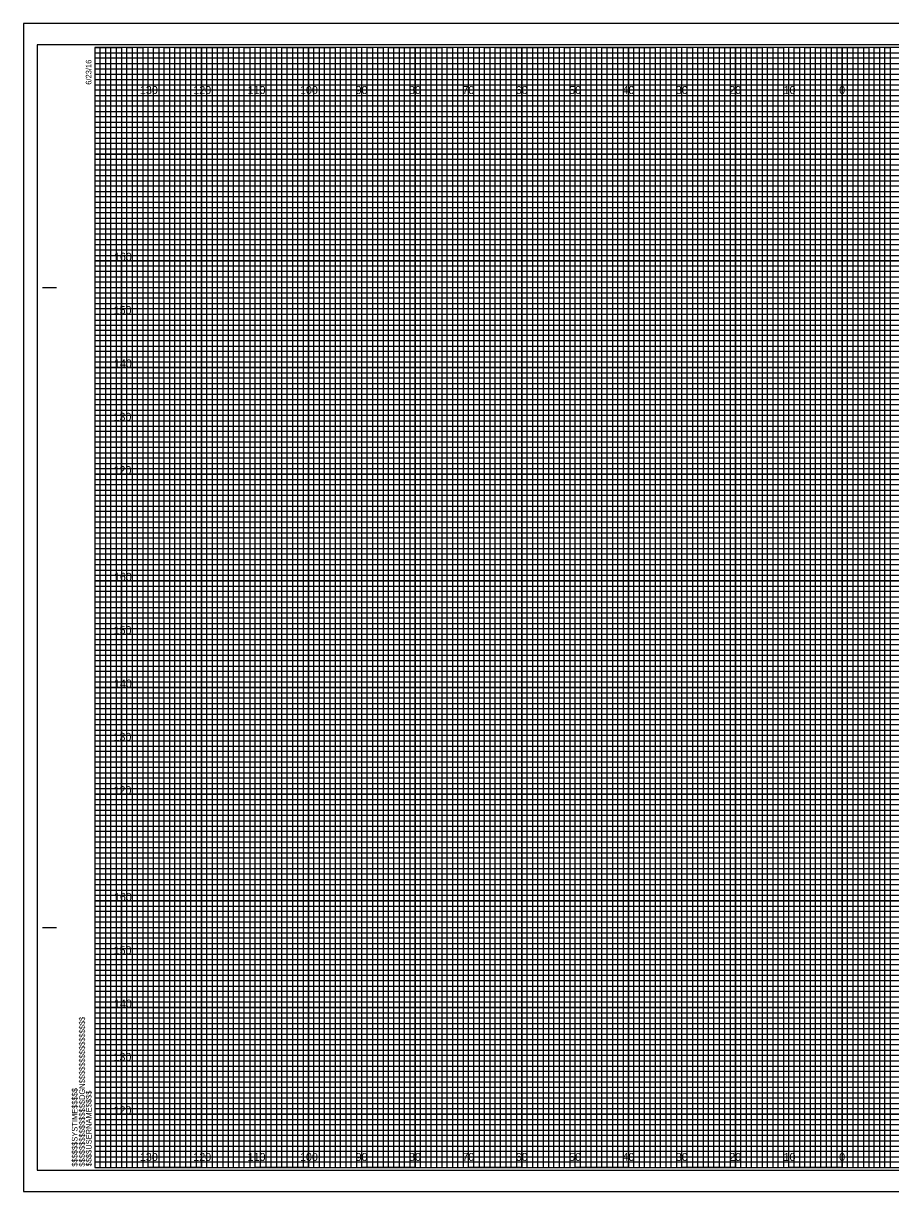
# Model space of a CAD drawing. Extents: x -13 to 323, y -5 to 3294.
# Drawn here: x -13.4 to 149.1, y 1315.5 to 1534.5 of the extents above; entities that cross this region are included whole.
import ezdxf

# ---------------------------------------------------------------- set-up
doc = ezdxf.new("R2010")
doc.units = 0
for name, color, linetype in [('Prop XS Elevation Labels', 7, 'Continuous'), ('Prop XS Offset Labels', 7, 'Continuous'), ('Scratch_Level_0', 7, 'Continuous'), ('Sheet Cross Section CELL', 7, 'Continuous'), ('Sheet Cross Section Grid Major CELL', 7, 'Continuous'), ('Sheet Cross Section Grid Middle CELL', 7, 'Continuous'), ('Sheet Cross Section Grid Minor 1 CELL', 7, 'Continuous'), ('Sheet Cross Section Grid Minor 2 CELL', 7, 'Continuous'), ('Sheet Cutting Line CELL', 7, 'Continuous'), ('Sheet DOT Grid CELL', 7, 'Continuous'), ('Sheet Plot Border Inside CELL', 7, 'Continuous'), ('Sheet Plot Border Outside CELL', 7, 'Continuous')]:
    doc.layers.add(name, color=color, linetype=linetype)

msp = doc.modelspace()

# ---------------------------------------------------------------- linework, layer by layer
at = {"layer": 'Scratch_Level_0'}
for points in [[(5, 1490), (310, 1490), (310, 1450), (5, 1450)], [(5, 1430), (315, 1430), (315, 1390), (5, 1390)], [(5, 1370), (315, 1370), (315, 1330), (5, 1330)]]:
    msp.add_lwpolyline(points, close=True, dxfattribs=at)
at = {"layer": 'Sheet Cross Section CELL'}
for p, q in [((-9.8, 1485), (-7.3, 1485)), ((-9.7, 1485), (-7.2, 1485)), ((-9.8, 1365), (-7.3, 1365)), ((-9.7, 1365), (-7.2, 1365)), ((0, 1320), (0, 1320)), ((0, 1320), (0, 1320)), ((0, 1320), (0, 1320)), ((0, 1320), (0, 1320)), ((0, 1320), (0, 1320)), ((0, 1320), (0, 1320)), ((0, 1320), (0, 1320))]:
    msp.add_line(p, q, dxfattribs=at)
msp.add_lwpolyline([(320, 1530), (0, 1530), (0, 1320), (320, 1320)], close=True, dxfattribs=at)
at = {"layer": 'Sheet Cross Section Grid Major CELL'}
for p, q in [((10, 1530), (0, 1530)), ((10, 1320), (10, 1530)), ((30, 1530), (20, 1530)), ((20, 1530), (20, 1320)), ((30, 1320), (30, 1530)), ((50, 1530), (40, 1530)), ((40, 1530), (40, 1320)), ((50, 1320), (50, 1530)), ((70, 1530), (60, 1530)), ((60, 1530), (60, 1320)), ((70, 1320), (70, 1530)), ((90, 1530), (80, 1530)), ((80, 1530), (80, 1320)), ((90, 1320), (90, 1530)), ((110, 1530), (100, 1530)), ((100, 1530), (100, 1320)), ((110, 1320), (110, 1530)), ((130, 1530), (120, 1530)), ((120, 1530), (120, 1320)), ((130, 1320), (130, 1530)), ((150, 1530), (140, 1530)), ((140, 1530), (140, 1320)), ((20, 1320), (10, 1320)), ((40, 1320), (30, 1320)), ((60, 1320), (50, 1320)), ((80, 1320), (70, 1320)), ((100, 1320), (90, 1320)), ((120, 1320), (110, 1320)), ((140, 1320), (130, 1320))]:
    msp.add_line(p, q, dxfattribs=at)
for points in [[(0, 1520), (320, 1520), (320, 1510), (0, 1510)], [(0, 1500), (320, 1500), (320, 1490), (0, 1490)], [(0, 1480), (320, 1480), (320, 1470), (0, 1470)], [(0, 1460), (320, 1460), (320, 1450), (0, 1450)], [(0, 1440), (320, 1440), (320, 1430), (0, 1430)], [(0, 1420), (320, 1420), (320, 1410), (0, 1410)], [(0, 1400), (320, 1400), (320, 1390), (0, 1390)], [(0, 1380), (320, 1380), (320, 1370), (0, 1370)], [(0, 1360), (320, 1360), (320, 1350), (0, 1350)], [(0, 1340), (320, 1340), (320, 1330), (0, 1330)]]:
    msp.add_lwpolyline(points, dxfattribs=at)
at = {"layer": 'Sheet Cross Section Grid Middle CELL'}
for points in [[(0, 1530), (5, 1530), (5, 1320), (15, 1320), (15, 1530), (25, 1530), (25, 1320), (35, 1320), (35, 1530), (45, 1530), (45, 1320), (55, 1320), (55, 1530), (65, 1530), (65, 1320), (75, 1320), (75, 1530), (85, 1530), (85, 1320), (95, 1320), (95, 1530), (105, 1530), (105, 1320), (115, 1320), (115, 1530), (125, 1530), (125, 1320), (135, 1320), (135, 1530), (145, 1530), (145, 1320), (155, 1320)], [(0, 1525), (275, 1525)], [(0, 1505), (320, 1505), (320, 1515), (0, 1515)], [(0, 1485), (320, 1485), (320, 1495), (0, 1495)], [(0, 1465), (320, 1465), (320, 1475), (0, 1475)], [(0, 1445), (320, 1445), (320, 1455), (0, 1455)], [(0, 1425), (320, 1425), (320, 1435), (0, 1435)], [(0, 1405), (320, 1405), (320, 1415), (0, 1415)], [(0, 1385), (320, 1385), (320, 1395), (0, 1395)], [(0, 1365), (320, 1365), (320, 1375), (0, 1375)], [(0, 1345), (320, 1345), (320, 1355), (0, 1355)], [(0, 1325), (320, 1325), (320, 1335), (0, 1335)]]:
    msp.add_lwpolyline(points, dxfattribs=at)
at = {"layer": 'Sheet Cross Section Grid Minor 1 CELL'}
for p, q in [((0, 1529), (260, 1529)), ((260, 1527.98), (0, 1527.98)), ((0, 1527.98), (0, 1527)), ((0, 1527), (260, 1527)), ((260, 1525.89), (0, 1525.89)), ((0, 1525.89), (0, 1524)), ((0, 1524), (320, 1524))]:
    msp.add_line(p, q, dxfattribs=at)
for points in [[(0, 1523), (270, 1523), (320, 1523), (320, 1522), (0, 1522)], [(0, 1521), (320, 1521), (320, 1519), (0, 1519)], [(0, 1518), (320, 1518), (320, 1517), (0, 1516.98)], [(0, 1516), (320, 1516), (320, 1514), (0, 1514)], [(0, 1513), (320, 1513), (320, 1512), (0, 1512)], [(0, 1511), (320, 1511), (320, 1509), (0, 1509)], [(0, 1508), (320, 1508), (320, 1507), (0, 1507)], [(0, 1506), (320, 1506), (320, 1504), (0, 1504)], [(0, 1503), (320, 1503), (320, 1502), (0, 1502)], [(0, 1501), (320, 1501), (320, 1499), (0, 1499)], [(0, 1498), (320, 1498), (320, 1497), (0, 1497)], [(0, 1496), (320, 1496), (320, 1493.95), (320, 1493), (320, 1492), (0, 1492)], [(0, 1494), (320, 1494), (320, 1493), (0, 1493)], [(0, 1491), (320, 1491), (320, 1489), (0, 1489.03)], [(0, 1489.03), (320, 1489), (320, 1488), (0, 1488)], [(0, 1487), (320, 1487), (320, 1486), (0, 1486)], [(0, 1484), (320, 1484), (320, 1483), (0, 1483)], [(0, 1482), (320, 1482), (320, 1481), (0, 1481)], [(-0.07, 1478.89), (320, 1478.89), (320, 1477.88), (-0.07, 1477.88)], [(0, 1477), (320, 1477), (320, 1476), (0, 1476)], [(0, 1474), (320, 1474), (320, 1473), (0, 1473)], [(0, 1472), (320, 1472), (320, 1471), (0, 1471)], [(0, 1469), (320, 1469), (320, 1468), (0, 1468)], [(0, 1467), (320, 1467), (320, 1466), (0, 1466)], [(0, 1464), (320, 1464), (320, 1463), (0, 1463)], [(0, 1462), (320, 1462), (320, 1461), (0, 1461)], [(0, 1459), (320, 1459), (319.99, 1457.98), (0, 1458)], [(0, 1457), (320, 1457), (320, 1456), (0, 1456)], [(0, 1454), (320, 1454), (320, 1453), (0, 1453)], [(0, 1452), (320, 1452), (320, 1451), (0, 1451)], [(0, 1449), (320, 1449), (320, 1448), (0, 1448)], [(0, 1447), (320, 1447), (320, 1446), (0, 1446)], [(0, 1444), (320, 1444), (320, 1443), (0, 1443)], [(0, 1442), (320, 1442), (320, 1441), (0, 1441)], [(0, 1439), (320, 1439), (320, 1438), (0, 1438)], [(0, 1436.99), (320.07, 1436.91), (320, 1436), (0, 1436)], [(0, 1434), (320, 1434), (320, 1433), (0, 1433)], [(0, 1432), (320, 1432), (320, 1431), (0, 1431)], [(0, 1429), (320, 1429), (320, 1428), (0, 1428)], [(0, 1427), (320, 1427), (320, 1426), (0, 1426)], [(0, 1424), (320, 1424), (320, 1423), (0, 1423)], [(0, 1422), (320, 1422), (320, 1421), (0, 1421)], [(0, 1419), (320, 1419), (320, 1418), (0, 1418)], [(0, 1417), (320, 1417), (320, 1416), (0, 1416)], [(0, 1414), (320, 1414), (320, 1413), (0, 1413)], [(0, 1412), (320, 1412), (320, 1411), (0, 1411)], [(0, 1409), (320, 1409), (320, 1408), (0, 1408)], [(0, 1407), (320, 1407), (320, 1406), (0, 1406)], [(0, 1404), (320, 1404), (320, 1403), (0, 1403)], [(0, 1402), (320, 1402), (320, 1401), (0, 1401)], [(0, 1399), (320, 1399), (319.99, 1397.98), (0, 1398)], [(0, 1397), (320, 1397), (320, 1396), (0, 1396)], [(0, 1394), (320, 1394), (320, 1393), (0, 1393)], [(0, 1392), (320, 1392), (320, 1391), (0, 1391)], [(0, 1389), (320, 1389), (320, 1388), (0, 1388)], [(0, 1387), (320, 1387), (320, 1386), (0, 1386)], [(0, 1384), (320, 1384), (320, 1383), (0, 1383)], [(0, 1382), (320, 1382), (320, 1381), (0, 1381)], [(0, 1379), (320, 1379), (320, 1378), (0, 1378)], [(0, 1376.99), (320.07, 1376.91), (320, 1376), (0, 1376)], [(0, 1374), (320, 1374), (320, 1373), (0, 1373)], [(0, 1372), (320, 1372), (320, 1371), (0, 1371)], [(0, 1369), (320, 1369), (320, 1368), (0, 1368)], [(0, 1367), (320, 1367), (320, 1366), (0, 1366)], [(0, 1364), (320, 1364), (320, 1363), (0, 1363)], [(0, 1362), (320, 1362), (320, 1361), (0, 1361)], [(0, 1359), (320, 1359), (320, 1358), (0, 1358)], [(0, 1357), (320, 1357), (320, 1356), (0, 1356)], [(0, 1354), (320, 1354), (320, 1353), (0, 1353)], [(0, 1352), (320, 1352), (320, 1351), (0, 1351)], [(0, 1349), (320, 1349), (320, 1348), (0, 1348)], [(0, 1347), (320, 1347), (320, 1346), (0, 1346)], [(0, 1344), (320, 1344), (320, 1343), (0, 1343)], [(0, 1342), (320, 1342), (320, 1341), (0, 1341)], [(0, 1339), (320, 1339), (320, 1338), (0, 1338)], [(0, 1337), (320, 1337), (320, 1336), (0, 1336)], [(0, 1334), (320, 1334), (320, 1333), (0, 1333)], [(0, 1332), (320, 1332), (320, 1331), (0, 1331)], [(0, 1329), (320, 1329), (320, 1328), (0, 1328)], [(0, 1327), (320, 1327), (320, 1326), (0, 1326)], [(0, 1324), (320, 1324), (320, 1323), (0, 1323)], [(0, 1322), (320, 1322), (320, 1321), (0, 1321)]]:
    msp.add_lwpolyline(points, dxfattribs=at)
at = {"layer": 'Sheet Cross Section Grid Minor 2 CELL'}
for points in [[(0, 1320), (1, 1320), (1, 1530), (2, 1530), (2, 1320)], [(2, 1320), (3, 1320), (3, 1530), (4, 1530), (4, 1320)], [(5, 1320), (6, 1320), (6, 1530), (7, 1530), (7, 1320)], [(7, 1320), (8, 1320), (8, 1530), (9, 1530), (9, 1320)], [(10, 1320), (11, 1320), (11, 1530), (12, 1530), (12, 1320)], [(12, 1320), (13, 1320), (13, 1530), (14, 1530), (14, 1320)], [(15, 1320), (16, 1320), (16, 1530), (17, 1530), (17, 1320)], [(17, 1320), (18, 1320), (18, 1530), (19, 1530), (19, 1320)], [(20, 1320), (21, 1320), (21, 1530), (22, 1530), (22, 1320)], [(22, 1320), (23, 1320), (23, 1530), (24, 1530), (24, 1320)], [(25, 1320), (26, 1320), (26, 1530), (27, 1530), (27, 1320)], [(27, 1320), (28, 1320), (28, 1530), (29, 1530), (29, 1320)], [(30, 1320), (31, 1320), (31, 1530), (32, 1530), (32, 1320)], [(32, 1320), (33, 1320), (33, 1530), (34, 1530), (34, 1320)], [(35, 1320), (36, 1320), (36, 1530), (37, 1530), (37, 1320)], [(37, 1320), (38, 1320), (38, 1530), (39, 1530), (39, 1320)], [(40, 1320), (41, 1320), (41, 1530), (42, 1530), (42, 1320)], [(42, 1320), (43, 1320), (43, 1530), (44, 1530), (44, 1320)], [(45, 1320), (46, 1320), (46, 1530), (47, 1530), (47, 1320)], [(47, 1320), (48, 1320), (48, 1530), (49, 1530), (49, 1320)], [(50, 1320), (51, 1320), (51, 1530), (52, 1530), (52, 1320)], [(52, 1320), (53, 1320), (53, 1530), (54, 1530), (54, 1320)], [(55, 1320), (56, 1320), (56, 1530), (57, 1530), (57, 1320)], [(57, 1320), (58, 1320), (58, 1530), (59, 1530), (59, 1320)], [(60, 1320), (61, 1320), (61, 1530), (62, 1530), (62, 1320)], [(62, 1320), (63, 1320), (63, 1530), (64, 1530), (64, 1320)], [(65, 1320), (66, 1320), (66, 1530), (67, 1530), (67, 1320)], [(67, 1320), (68, 1320), (68, 1530), (69, 1530), (69, 1320)], [(70, 1320), (71, 1320), (71, 1530), (72, 1530), (72, 1320)], [(72, 1320), (73, 1320), (73, 1530), (74, 1530), (74, 1320)], [(75, 1320), (76, 1320), (76, 1530), (77, 1530), (77, 1320)], [(77, 1320), (78, 1320), (78, 1530), (79, 1530), (79, 1320)], [(80, 1320), (81, 1320), (81, 1530), (82, 1530), (82, 1320)], [(82, 1320), (83, 1320), (83, 1530), (84, 1530), (84, 1320)], [(85, 1320), (86, 1320), (86, 1530), (87, 1530), (87, 1320)], [(87, 1320), (88, 1320), (88, 1530), (89, 1530), (89, 1320)], [(90, 1320), (91, 1320), (91, 1530), (92, 1530), (92, 1320)], [(92, 1320), (93, 1320), (93, 1530), (94, 1530), (94, 1320)], [(95, 1320), (96, 1320), (96, 1530), (97, 1530), (97, 1320)], [(97, 1320), (98, 1320), (98, 1530), (99, 1530), (99, 1320)], [(100, 1320), (101, 1320), (101, 1530), (102, 1530), (102, 1320)], [(102, 1320), (103, 1320), (103, 1530), (104, 1530), (104, 1320)], [(105, 1320), (106, 1320), (106, 1530), (107, 1530), (107, 1320)], [(107, 1320), (108, 1320), (108, 1530), (109, 1530), (109, 1320)], [(110, 1320), (111, 1320), (111, 1530), (112, 1530), (112, 1320)], [(112, 1320), (113, 1320), (113, 1530), (114, 1530), (114, 1320)], [(115, 1320), (116, 1320), (116, 1530), (117, 1530), (117, 1320)], [(117, 1320), (118, 1320), (118, 1530), (119, 1530), (119, 1320)], [(120, 1320), (121, 1320), (121, 1530), (122, 1530), (122, 1320)], [(122, 1320), (123, 1320), (123, 1530), (124, 1530), (124, 1320)], [(125, 1320), (126, 1320), (126, 1530), (127, 1530), (127, 1320)], [(127, 1320), (128, 1320), (128, 1530), (129, 1530), (129, 1320)], [(130, 1320), (131, 1320), (131, 1530), (132, 1530), (132, 1320)], [(132, 1320), (133, 1320), (133, 1530), (134, 1530), (134, 1320)], [(135, 1320), (136, 1320), (136, 1530), (137, 1530), (137, 1320)], [(137, 1320), (138, 1320), (138, 1530), (139, 1530), (139, 1320)], [(140, 1320), (141, 1320), (141, 1530), (142, 1530), (142, 1320)], [(142, 1320), (143, 1320), (143, 1530), (144, 1530), (144, 1320)], [(145, 1320), (146, 1320), (146, 1530), (147, 1530), (147, 1320)], [(147, 1320), (148, 1320), (148, 1530), (149, 1530), (149, 1320)]]:
    msp.add_lwpolyline(points, dxfattribs=at)
at = {"layer": 'Sheet Cutting Line CELL'}
for p, q in [((323.3, 1534.5), (-13.4, 1534.5)), ((-13.4, 1534.5), (-13.4, 1315.5)), ((-13.4, 1315.5), (323.3, 1315.5))]:
    msp.add_line(p, q, dxfattribs=at)
at = {"layer": 'Sheet DOT Grid CELL'}
for p, q in [((10, 1320), (10, 1530)), ((20, 1320), (20, 1530)), ((30, 1320), (30, 1530)), ((40, 1320), (40, 1530)), ((50, 1320), (50, 1530)), ((60, 1320), (60, 1530)), ((70, 1320), (70, 1530)), ((80, 1320), (80, 1530)), ((90, 1320), (90, 1530)), ((100, 1320), (100, 1530)), ((110, 1320), (110, 1530)), ((120, 1320), (120, 1530)), ((130, 1320), (130, 1530)), ((140, 1320), (140, 1530)), ((0, 1520), (320, 1520)), ((0, 1510), (320, 1510)), ((0, 1500), (320, 1500)), ((0, 1490), (320, 1490)), ((0, 1480), (320, 1480)), ((0, 1470), (320, 1470)), ((0, 1460), (320, 1460)), ((0, 1450), (320, 1450)), ((0, 1440), (320, 1440)), ((0, 1430), (320, 1430)), ((0, 1420), (320, 1420)), ((0, 1410), (320, 1410)), ((0, 1400), (320, 1400)), ((0, 1390), (320, 1390)), ((0, 1380), (320, 1380)), ((0, 1370), (320, 1370)), ((0, 1360), (320, 1360)), ((0, 1350), (320, 1350)), ((0, 1340), (320, 1340)), ((0, 1330), (320, 1330))]:
    msp.add_line(p, q, dxfattribs=at)
at = {"layer": 'Sheet Plot Border Inside CELL'}
msp.add_lwpolyline([(-10.8, 1319.5), (322.4, 1319.5), (322.4, 1530.5), (-10.8, 1530.5)], close=True, dxfattribs=at)
at = {"layer": 'Sheet Plot Border Outside CELL'}
msp.add_lwpolyline([(-13.4, 1315.5), (323.3, 1315.5), (323.3, 1534.5), (-13.4, 1534.5)], close=True, dxfattribs=at)

# ---------------------------------------------------------------- texts
at = {"layer": 'Prop XS Elevation Labels'}
for s, p in [('160', (3.57, 1490)), ('150', (3.52, 1480)), ('140', (3.57, 1470)), ('130', (3.49, 1460)), ('120', (3.5, 1450)), ('160', (3.57, 1430)), ('150', (3.52, 1420)), ('140', (3.57, 1410)), ('130', (3.49, 1400)), ('120', (3.5, 1390)), ('160', (3.57, 1370)), ('150', (3.52, 1360)), ('140', (3.57, 1350)), ('130', (3.49, 1340)), ('120', (3.5, 1330))]:
    msp.add_text(s, height=1.5, dxfattribs=at).set_placement(p)
at = {"layer": 'Prop XS Offset Labels'}
for s, p in [('130', (8.44, 1521.25)), ('120', (18.44, 1521.25)), ('110', (28.62, 1521.25)), ('100', (38.44, 1521.25)), ('90', (48.86, 1521.25)), ('80', (58.86, 1521.25)), ('70', (68.86, 1521.25)), ('60', (78.86, 1521.25)), ('50', (88.86, 1521.25)), ('40', (98.86, 1521.25)), ('30', (108.86, 1521.25)), ('20', (118.86, 1521.25)), ('10', (129.04, 1521.25)), ('0', (139.45, 1521.25)), ('0', (139.45, 1521.25)), ('130', (8.44, 1321.25)), ('120', (18.44, 1321.25)), ('110', (28.62, 1321.25)), ('100', (38.44, 1321.25)), ('90', (48.86, 1321.25)), ('80', (58.86, 1321.25)), ('70', (68.86, 1321.25)), ('60', (78.86, 1321.25)), ('50', (88.86, 1321.25)), ('40', (98.86, 1321.25)), ('30', (108.86, 1321.25)), ('20', (118.86, 1321.25)), ('10', (129.04, 1321.25)), ('0', (139.45, 1321.25)), ('0', (139.45, 1321.25))]:
    msp.add_text(s, height=1.5, dxfattribs=at).set_placement(p)
at = {"layer": 'Sheet Cross Section CELL'}
for s, p in [('6/23/16', (-0.65, 1523)), ('$$$$$$$$$$$$$$$$DGN$$$$$$$$$$$$$$$$', (-1.88, 1320.18)), ('$$$$$$SYSTIME$$$$$', (-3.26, 1320.18)), ('$$$$USERNAME$$$$', (-0.62, 1320.23))]:
    msp.add_text(s, height=1.05, rotation=90, dxfattribs=at).set_placement(p)

doc.saveas('drawing.dxf')
